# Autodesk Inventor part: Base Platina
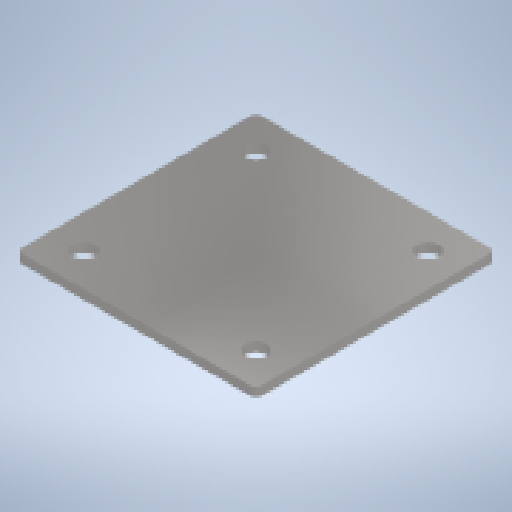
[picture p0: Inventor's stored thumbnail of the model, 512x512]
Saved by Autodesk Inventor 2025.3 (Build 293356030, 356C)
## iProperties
Created: 2025-10
Part Number: Base Platina
Material: Hierro, fundido
Document SubType Name: Modeling
Designer: Asus
Density: 7.15 g/cm^3
Appearance: Inoxidable - Bruñido
Author: Asus
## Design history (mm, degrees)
sketch "Boceto1"
  geometry: L1 (-125, -125)-(125, -125); L2 (125, -125)-(125, 125); L3 (125, 125)-(-125, 125); L4 (-125, 125)-(-125, -125); L5 (-125, -125)-(125, 125); L6 (125, -125)-(-125, 125); 1 further point
  constraints: 12 end point, 2 midpoint, 2 parallel, 1 horizontal, 1 perpendicular
  dimensions: "d0" = 250 distance of L1.end L2.end; "d1" = 250 distance of L1.start L1.end (= d0)
extrude "Extrusión1" new body sketch "Boceto1" distance "d2" = 9.525; taper "d3" = 0 deg
sketch "Boceto2"
  geometry: L1 (90, 90)-(-90, 90); L2 (-90, 90)-(-90, -90); L3 (-90, -90)-(90, -90); L4 (90, -90)-(90, 90); L5 (90, 90)-(-90, -90); L6 (-90, 90)-(90, -90); C1 r 84.138 at (0, 0); 5 further points
  constraints: 12 end point, 5 coincident, 2 midpoint, 2 parallel, 1 centre point, 1 horizontal, 1 perpendicular
  dimensions: "d4" = 168.275 diameter of C1; "d5" = 180 distance of L1.end L2.end (= d6); "d6" = 180 distance of L1.start L1.end
hole "Agujero1" sketch "Boceto2" at (-90, -90), (-90, 90), (90, 90), (90, -90) diameter "d7" = 22; stored, may be unused: countersink angle "d11" = 90 deg, drill point angle "d13" = 118 deg; dims "d8" = 6, "d9" = 4, "d10" = 2, "d12" = 8
fillet "Empalme1" dims "d14" = 5
node "Sólido1"
